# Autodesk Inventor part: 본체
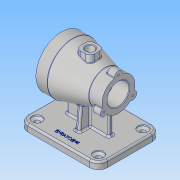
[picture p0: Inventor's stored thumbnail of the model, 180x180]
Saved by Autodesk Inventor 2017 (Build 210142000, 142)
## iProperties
Part Number: 본체
Material: 알루미늄 6061
Document SubType Name: Modeling
Designer: user
Density: 2.7 g/cm^3
Appearance: 알루미늄 - 평지
Mass: 1218.8 g
Surface Area: 896.758 cm^2
Volume: 451.408 cm^3
Author: user
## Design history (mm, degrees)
sketch "스케치1"
  geometry: L1 (70, 55)-(-70, 55); L2 (-70, 55)-(-70, -55); L3 (-70, -55)-(70, -55); L4 (70, -55)-(70, 55); L5 (70, 55)-(-70, -55); L6 (-70, 55)-(70, -55); 1 further point
  constraints: 12 end point, 2 midpoint, 2 parallel, 1 horizontal, 1 perpendicular
  dimensions: "d0" = 110 distance of L3.end L1.start; "d1" = 140 distance of L1.start L1.end
extrude "돌출1" new body sketch "스케치1" distance "d2" = 12; taper "d3" = 0 deg
sketch "스케치2" dims "d67" = 60 deg
  geometry: L1 (70, 55)-(-70, 55) reference; L2 (-70, 55)-(-70, -55) reference; 5 further points
  constraints: 2 horizontal alignment, 2 vertical alignment
  dimensions: "d4" = 108 distance of point (54, 39) point (-54, 39); "d5" = 16 distance from line of L2 point (-54, 39); "d6" = 16 distance from line of L1 point (-54, 39); "d7" = 78 distance of point (-54, 39) point (-54, -39)
hole "구멍1" sketch "스케치2" at (-54, 39), (-54, -39), (54, -39), (54, 39) diameter "d8" = 18; stored, may be unused: countersink angle "d12" = 90 deg, drill point angle "d14" = 118 deg; dims "d9" = 6, "d10" = 4, "d11" = 2, "d13" = 2
sketch "스케치3"
  geometry: C1 r 9 at (54, -39) reference; C2 r 9 at (-54, 39) reference; C3 r 9 at (-54, -39) reference; C4 r 9 at (54, 39) reference; 5 further points
  constraints: 4 coincident
hole "구멍2" sketch "스케치3" at (-54, 39), (-54, -39), (54, -39), (54, 39) diameter "d15" = 9; stored, may be unused: countersink angle "d19" = 90 deg, drill point angle "d21" = 118 deg; dims "d16" = 6, "d17" = 4, "d18" = 2, "d20" = 2
sketch "스케치4"
  geometry: L1 (-50, 82)-(50, 82); L2 (50, 82)-(50, 111); L3 (50, 111)-(27, 111); L4 (27, 111)-(-30, 127); L5 (-30, 127)-(-50, 127); L6 (-50, 127)-(-50, 82); L7 (-70, 0)-(70, 0) reference; 3 further points
  constraints: 12 end point, 3 perpendicular, 2 horizontal, 2 midpoint, 1 vertical alignment
  dimensions: "d22" = 82 distance between parallel lines of L1 L7; "d23" = 90 diameter of L5 L1; "d24" = 58 diameter of L3 L1; "d25" = 100 distance of L1.start L1.end; "d26" = 20 distance of L4.end L5.end; "d27" = 23 distance of L2.end L3.end
revolve "회전1" sketch "스케치4" stored, may be unused: angle "d28" = 90 deg
sketch "스케치6"
  geometry: L1 (-37, 70)-(37, 70); L2 (37, 70)-(37, 0); L3 (37, 0)-(-37, 0); L4 (-37, 0)-(-37, 70); L5 (70, 0)-(-70, 0) reference; 2 further points
  constraints: 8 end point, 2 parallel, 1 coincident, 1 collinear, 1 horizontal, 1 midpoint, 1 perpendicular
  dimensions: "d33" = 74 distance of L2.end L3.end; "d34" = 70 distance of L1.end L2.end
extrude "돌출3" join sketch "스케치6" stored distance "d35" = 8; taper "d36" = 0 deg
sketch "스케치7" dims "d84" = 3
  geometry: L1 (60, 18.751)-(0, 24); L2 (0, 24)-(0, -24); L3 (0, -24)-(60, -18.751); L4 (60, -18.751)-(60, 18.751); L5 (0, -55)-(0, 55) reference; L6 (12, -55)-(12, 55) reference; 3 further points
  constraints: 8 end point, 2 midpoint, 1 coincident, 1 collinear, 1 parallel, 1 vertical
  dimensions: "d37" = 95 deg angle of L3 L6; "d38" = 95 deg angle of L1 L6; "d39" = 24 distance of L1.end point (0, 0); "d40" = 60 distance between parallel lines of L2 L4
extrude "돌출4" join sketch "스케치7" stored distance "d41" = 8; taper "d42" = 0 deg
sketch "스케치8"
  geometry: L1 (-50, 37)-(-50, 127) reference; L2 (-50, 82)-(50, 82); L3 (50, 82)-(50, 101); L4 (50, 53)-(50, 111) reference; L5 (20, 101)-(20, 107); L6 (20, 107)-(-27, 107); L7 (-27, 107)-(-27, 113); L8 (-27, 113)-(-50, 113); L9 (-50, 113)-(-50, 82); L10 (20, 101)-(50, 101); L11 (70, 0)-(-70, 0) reference; 1 further point
  constraints: 16 end point, 4 perpendicular, 2 horizontal, 1 collinear, 1 midpoint, 1 point on line, 1 vertical
  dimensions: "d43" = 62 diameter of L8 L2; "d44" = 50 diameter of L6 L2; "d45" = 38 diameter of L10 L2; "d46" = 23 distance of L7.end L8.end; "d47" = 30 distance of L5.start L3.end; "d48" = 82 distance between parallel lines of L11 L2
revolve "회전2" sketch "스케치8" stored, may be unused: angle "d49" = 90 deg
sketch "스케치9"
  geometry: L1 (0, 0)-(0, 29); L2 (0, 0)-(-25.115, -14.5); L3 (0, 0)-(25.115, -14.5); C1 r 7 at (-25.115, -14.5); C2 r 7 at (0, 29); C3 r 7 at (25.115, -14.5); A1 r 29 centre (0, 0) between (0, 29) and (-25.115, -14.5) reference; 1 further point
  constraints: 6 end point, 3 centre point, 3 coincident, 3 point on circle, 1 vertical
  dimensions: "d50" = 120 deg angle of L2 L1; "d51" = 120 deg angle of L1 L3; "d52" = 14 diameter of C1; "d53" = 14 diameter of C2; "d54" = 14 diameter of C3
extrude "돌출5" join sketch "스케치9" distance "d55" = 15; taper "d56" = 0 deg
node "작업 평면1"
sketch "스케치10"
  geometry: L1 (12.5, 12.5)-(-12.5, 12.5); L2 (-12.5, 12.5)-(-12.5, -12.5); L3 (-12.5, -12.5)-(12.5, -12.5); L4 (12.5, -12.5)-(12.5, 12.5); L5 (12.5, 12.5)-(-12.5, -12.5); L6 (-12.5, 12.5)-(12.5, -12.5); 1 further point
  constraints: 12 end point, 2 midpoint, 2 parallel, 1 horizontal, 1 perpendicular
  dimensions: "d58" = 25 distance of L3.end L2.end; "d59" = 25 distance of L2.end L1.end
extrude "돌출6" join sketch "스케치10" stored distance "d60" = 15; taper "d61" = 0 deg
sketch "스케치11"
  geometry: C1 r 7.5 at (0, 0); 1 further point
  constraints: 1 centre point, 1 coincident
  dimensions: "d62" = 15 diameter of C1
extrude "돌출7" cut sketch "스케치11" distance "d63" = 50; taper "d64" = 0 deg
sketch "스케치12"
  geometry: L1 (0, 0)-(0, 40); L2 (-34.641, 20)-(0, 0); L3 (-34.641, -20)-(0, 0); L4 (0, -40)-(0, 0); L5 (34.641, -20)-(0, 0); L6 (34.641, 20)-(0, 0); C1 r 31 at (0, 0) reference; A1 r 40 centre (0, 0) between (0, 40) and (-34.641, 20); 1 further point
  constraints: 12 end point, 6 point on circle, 2 vertical, 1 centre point, 1 coincident
  dimensions: "d65" = 80 diameter of A1; "d66" = 60 deg angle of L1 L2; "d67" = 60 deg angle of L3 L2; "d68" = 60 deg angle of L5 L4; "d69" = 60 deg angle of L6 L5
hole "구멍3" sketch "스케치12" at (0, 40), (-34.641, 20), (-34.641, -20), (0, -40), (34.641, -20), (34.641, 20) diameter "d70" = 3.242; stored, may be unused: countersink angle "d74" = 90 deg, drill point angle "d76" = 118 deg; dims "d71" = 9, "d72" = 4, "d73" = 2, "d75" = 11
sketch "스케치13"
  geometry: A1 r 7 centre (0, 0) between (6.949, -0.845) and (-6.949, -0.845) reference; A2 r 7 centre (-25.115, -43.5) between (-27.858, -37.06) and (-20.909, -49.095) reference; A3 r 7 centre (25.115, -43.5) between (20.909, -49.095) and (27.858, -37.06) reference; A4 r 29 centre (0, -29) between (4, -57.723) and (-4, -57.723) reference; 4 further points
  constraints: 3 coincident
hole "구멍4" sketch "스케치13" at (0, 0), (-25.115, -43.5), (25.115, -43.5) diameter "d77" = 3.242; stored, may be unused: countersink angle "d81" = 90 deg, drill point angle "d83" = 118 deg; dims "d78" = 9, "d79" = 4, "d80" = 2, "d82" = 11
fillet "모깎기1" dims "d84" = 3
fillet "모깎기3" dims "d86" = 8, "d87" = 1
chamfer "모따기1" distance "d88" = 1; stored, may be unused: second distance "d89" = 2, angle "d90" = 45 deg
fillet "모깎기4" dims "d91" = 3
fillet "모깎기5" dims "d92" = 3
fillet "모깎기6" dims "d93" = 1, "d94" = 3
fillet "모깎기7" dims "d95" = 16
node "작업 평면2"
sketch "스케치14"
  geometry: L1 (-54, -55)-(54, -55) reference; 2 further points
  constraints: 1 vertical alignment, 1 other
  dimensions: "d97" = 15 distance from line of point (0, -40) L1
feature "엠보싱1" sketch "스케치14" dims "d0" = 110, "d1" = 140, "d98" = 0.5, "d99" = 0
fillet "모깎기8" dims "d100" = 1
node "솔리드1"
other parameters: "d57" = 127, "d96" = 5
